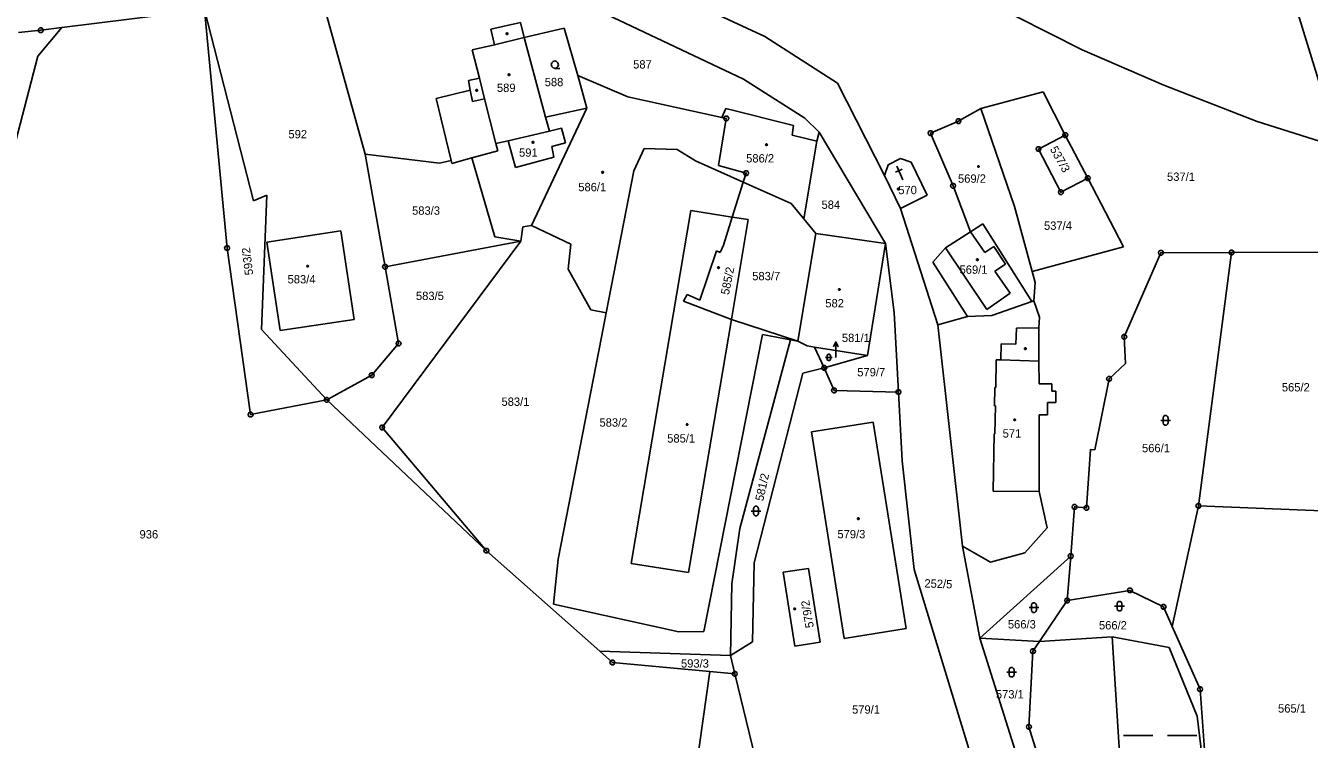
# Model space of a CAD drawing. Extents: x -812394 to -807601, y -1013098 to -1009266.
# Drawn here: x -809265.1 to -809003.5, y -1011807.7 to -1011662.3 of the extents above; entities that cross this region are included whole.
import ezdxf

# ---------------------------------------------------------------- set-up
doc = ezdxf.new("R2010")
doc.units = 0
for name, color, linetype in [('KN_HRANICE', 7, 'Continuous'), ('KN_KULTURY', 7, 'Continuous'), ('KN_MEZNIKY', 7, 'Continuous'), ('KN_PARCELY', 7, 'Continuous'), ('KN_SLUCKY', 7, 'Continuous')]:
    doc.layers.add(name, color=color, linetype=linetype)

# ---------------------------------------------------------------- blocks, each defined once
blk = doc.blocks.new('304')
blk.add_lwpolyline([(0, 0), (-0.38, 0.1), (-0.65, 0.37), (-0.75, 0.74), (-0.65, 1.11), (-0.38, 1.38), (-0.01, 1.48), (0.36, 1.38), (0.63, 1.11), (0.73, 0.73), (0.63, 0.35), (0.36, 0.08), (-0.02, -0.02), (0.98, -0.02)])
blk = doc.blocks.new('316')
for points in [[(-1, 1), (0.27, 1), (1, 1)], [(-0.5, 1.5), (-0.4, 1.79), (-0.15, 1.97), (0.16, 1.97), (0.41, 1.79), (0.51, 1.5), (0.51, 0.5), (0.41, 0.21), (0.16, 0.03), (-0.15, 0.03), (-0.4, 0.21), (-0.5, 0.5), (-0.5, 1.5)]]:
    blk.add_lwpolyline(points)
blk = doc.blocks.new('NAHRADNI_SYMBOL')
blk.add_lwpolyline([(0.09, 0.15), (0.18, 0), (0.09, -0.15), (-0.09, -0.15), (-0.18, 0), (-0.09, 0.15), (0.09, 0.15)])
blk = doc.blocks.new('803')
for p, q in [((-7.5, 0), (-1.5, 0)), ((1.5, 0), (7.5, 0))]:
    blk.add_line(p, q)
blk = doc.blocks.new('10292')
blk.add_line((0, 3), (0, 0))
blk.add_lwpolyline([(-0.5, 2), (0, 3), (0.5, 2)])
blk = doc.blocks.new('402')
blk.add_lwpolyline([(0.09, 0.15), (0.18, 0), (0.09, -0.15), (-0.09, -0.15), (-0.18, 0), (-0.09, 0.15), (0.09, 0.15)])
blk = doc.blocks.new('4091')
for p, q in [((0, 0), (0, 3)), ((0.75, 2), (-0.75, 2))]:
    blk.add_line(p, q)
blk = doc.blocks.new('105')
blk.add_line((-0.12, 0), (0.12, 0))
blk.add_lwpolyline([(0.15, 0.48), (0.4, 0.3), (0.5, 0.01), (0.4, -0.28), (0.15, -0.46), (-0.16, -0.46), (-0.41, -0.28), (-0.51, 0.01), (-0.41, 0.3), (-0.16, 0.48), (0.15, 0.48)])

msp = doc.modelspace()

# ---------------------------------------------------------------- linework, layer by layer
at = {"layer": 'KN_HRANICE'}
for p, q in [((-809015.5, -1011628.37), (-808997.45, -1011687.11)), ((-809118.81, -1011673.24), (-809167.11, -1011650.32)), ((-809144.03, -1011650.78), (-809114.47, -1011664.51)), ((-809204.84, -1011656.21), (-809195.9, -1011688.5)), ((-809257.74, -1011662.73), (-809228.66, -1011659.08)), ((-809218.66, -1011698.01), (-809228.66, -1011659.08)), ((-809228.66, -1011659.08), (-809224.05, -1011707.64)), ((-809164.26, -1011661.71), (-809170.27, -1011663.04)), ((-809164.26, -1011661.71), (-809163.49, -1011664.76)), ((-809063.24, -1011660.46), (-809049.78, -1011667.23)), ((-809266.53, -1011663.7), (-809262.03, -1011663.27)), ((-809262.63, -1011668.57), (-809257.74, -1011662.73)), ((-809262.03, -1011663.27), (-809257.74, -1011662.73)), ((-809170.27, -1011663.04), (-809169.57, -1011666.21)), ((-809163.49, -1011664.76), (-809155.36, -1011662.84)), ((-809163.49, -1011664.76), (-809159.14, -1011680.97)), ((-809155.36, -1011662.84), (-809152.6, -1011672.5)), ((-809114.47, -1011664.51), (-809099.63, -1011674.03)), ((-809174.08, -1011667.28), (-809169.57, -1011666.21)), ((-809174.08, -1011667.28), (-809172.62, -1011673.04)), ((-809049.78, -1011667.23), (-809033.12, -1011674.42)), ((-809269.33, -1011694.44), (-809262.63, -1011668.57)), ((-809174.88, -1011673.53), (-809172.62, -1011673.04)), ((-809142.39, -1011676.83), (-809152.6, -1011672.5)), ((-809152.6, -1011672.5), (-809150.71, -1011679.14)), ((-809181.41, -1011677.14), (-809174.49, -1011675.49)), ((-809174.49, -1011675.49), (-809174.88, -1011673.53)), ((-809106.3, -1011681.14), (-809118.81, -1011673.24)), ((-809090.09, -1011692.88), (-809099.63, -1011674.03)), ((-809033.12, -1011674.42), (-809014.11, -1011681.87)), ((-809178.41, -1011689.79), (-809181.41, -1011677.14)), ((-809123.26, -1011681.02), (-809142.39, -1011676.83)), ((-809070.44, -1011679.2), (-809057.74, -1011675.8)), ((-809057.74, -1011675.8), (-809053.23, -1011684.62)), ((-809162.04, -1011703.02), (-809150.71, -1011679.14)), ((-809150.71, -1011679.14), (-809159.14, -1011680.97)), ((-809123.26, -1011681.02), (-809122.44, -1011679.19)), ((-809122.44, -1011679.19), (-809108.6, -1011682.65)), ((-809074.31, -1011681.39), (-809070.44, -1011679.2)), ((-809063.59, -1011699.18), (-809070.44, -1011679.2)), ((-809159.14, -1011680.97), (-809158.38, -1011683.82)), ((-809123.9, -1011690.84), (-809122.31, -1011681.23)), ((-809122.31, -1011681.23), (-809123.26, -1011681.02)), ((-809108.6, -1011682.65), (-809108.92, -1011684.62)), ((-809103.4, -1011684.01), (-809106.3, -1011681.14)), ((-809080.69, -1011684.21), (-809074.99, -1011681.77)), ((-809074.99, -1011681.77), (-809074.31, -1011681.39)), ((-809014.11, -1011681.87), (-808997.45, -1011687.11)), ((-809169.26, -1011686.36), (-809166.74, -1011685.77)), ((-809166.74, -1011685.77), (-809158.38, -1011683.82)), ((-809108.92, -1011684.62), (-809103.84, -1011685.87)), ((-809103.84, -1011685.87), (-809106.54, -1011701.66)), ((-809103.4, -1011684.01), (-809103.84, -1011685.87)), ((-809103.4, -1011684.01), (-809089.88, -1011706.73)), ((-809076.1, -1011694.95), (-809080.69, -1011684.21)), ((-809053.23, -1011684.62), (-809058.69, -1011687.46)), ((-809048.65, -1011693.42), (-809053.23, -1011684.62)), ((-809195.9, -1011688.5), (-809180.76, -1011690.33)), ((-809195.9, -1011688.5), (-809191.85, -1011711.45)), ((-809174.17, -1011689.22), (-809168.89, -1011687.82)), ((-809169.26, -1011686.36), (-809168.89, -1011687.82)), ((-809139.05, -1011687.35), (-809141.13, -1011691.93)), ((-809132.32, -1011687.55), (-809139.05, -1011687.35)), ((-809128.57, -1011689.88), (-809132.32, -1011687.55)), ((-809058.69, -1011687.46), (-809054.11, -1011696.26)), ((-809180.76, -1011690.33), (-809178.41, -1011689.79)), ((-809178.41, -1011689.79), (-809178.26, -1011690.42)), ((-809178.26, -1011690.42), (-809174.17, -1011689.22)), ((-809174.17, -1011689.22), (-809169.49, -1011705.38)), ((-809118.86, -1011694.22), (-809128.57, -1011689.88)), ((-809118.27, -1011692.36), (-809123.9, -1011690.84)), ((-809090.09, -1011692.88), (-809089.34, -1011690.67)), ((-809089.34, -1011690.67), (-809086.85, -1011689.4)), ((-809086.85, -1011689.4), (-809084.66, -1011690.15)), ((-809084.66, -1011690.15), (-809081.39, -1011696.85)), ((-809141.13, -1011691.93), (-809146.78, -1011720.87)), ((-809118.86, -1011694.22), (-809118.27, -1011692.36)), ((-809086.82, -1011699.58), (-809090.09, -1011692.88)), ((-809054.11, -1011696.26), (-809048.65, -1011693.42)), ((-809048.65, -1011693.42), (-809041.37, -1011707.4)), ((-809121.11, -1011701.32), (-809118.86, -1011694.22)), ((-809109.13, -1011698.56), (-809118.86, -1011694.22)), ((-809072.55, -1011704.3), (-809076.1, -1011694.95)), ((-809215.97, -1011696.83), (-809218.66, -1011698.01)), ((-809217.07, -1011724.24), (-809215.97, -1011696.83)), ((-809106.54, -1011701.66), (-809109.13, -1011698.56)), ((-809081.39, -1011696.85), (-809086.82, -1011699.58)), ((-809059.99, -1011712.39), (-809063.59, -1011699.18)), ((-809129.54, -1011699.97), (-809133.14, -1011721.27)), ((-809121.11, -1011701.32), (-809129.54, -1011699.97)), ((-809121.11, -1011701.32), (-809122.92, -1011707.03)), ((-809121.28, -1011722.18), (-809117.84, -1011701.84)), ((-809117.84, -1011701.84), (-809121.11, -1011701.32)), ((-809104.04, -1011704.66), (-809106.54, -1011701.66)), ((-809079.24, -1011723.27), (-809086.82, -1011699.58)), ((-809215.97, -1011706.41), (-809200.9, -1011704.12)), ((-809200.9, -1011704.12), (-809198.16, -1011722.17)), ((-809163.75, -1011703.34), (-809164.16, -1011706.25)), ((-809162.04, -1011703.02), (-809163.75, -1011703.34)), ((-809162.04, -1011703.02), (-809154.01, -1011706.83)), ((-809077.65, -1011707.56), (-809072.55, -1011704.3)), ((-809072.55, -1011704.3), (-809070.01, -1011702.67)), ((-809070.01, -1011702.67), (-809060.03, -1011718.52)), ((-809213.22, -1011724.44), (-809215.97, -1011706.41)), ((-809164.16, -1011706.25), (-809192.44, -1011744.19)), ((-809191.85, -1011711.45), (-809164.16, -1011706.25)), ((-809164.16, -1011706.25), (-809169.49, -1011705.38)), ((-809154.01, -1011706.83), (-809154.57, -1011711.95)), ((-809122.92, -1011707.03), (-809123.54, -1011708.51)), ((-809104.04, -1011704.66), (-809107.75, -1011726.64)), ((-809089.88, -1011706.73), (-809104.04, -1011704.66)), ((-809093.54, -1011729.56), (-809089.88, -1011706.73)), ((-809088.11, -1011720.75), (-809089.88, -1011706.73)), ((-809224.05, -1011707.64), (-809219.25, -1011741.58)), ((-809124.3, -1011708.21), (-809127.72, -1011718.26)), ((-809123.54, -1011708.51), (-809124.3, -1011708.21)), ((-809080.26, -1011710.48), (-809077.65, -1011707.56)), ((-809041.37, -1011707.4), (-809059.99, -1011712.39)), ((-809041.21, -1011725.74), (-809033.74, -1011708.6)), ((-809033.74, -1011708.6), (-809019.35, -1011708.55)), ((-809019.35, -1011708.55), (-809026.09, -1011760.16)), ((-809019.35, -1011708.55), (-808992.34, -1011708.44)), ((-809191.85, -1011711.45), (-809189.09, -1011727.11)), ((-809154.57, -1011711.95), (-809149.9, -1011720.22)), ((-809080.26, -1011710.48), (-809073.13, -1011721.6)), ((-809059.99, -1011712.39), (-809059.38, -1011714.65)), ((-809059.38, -1011714.65), (-809059.65, -1011718.39)), ((-809130.26, -1011717.12), (-809131.05, -1011718.48)), ((-809127.72, -1011718.26), (-809130.26, -1011717.12)), ((-809131.05, -1011718.48), (-809121.28, -1011722.18)), ((-809060.03, -1011718.52), (-809068.19, -1011721.35)), ((-809059.65, -1011718.39), (-809060.03, -1011718.52)), ((-809059.65, -1011718.39), (-809058.51, -1011721.71)), ((-809198.16, -1011722.17), (-809213.22, -1011724.44)), ((-809149.9, -1011720.22), (-809146.78, -1011720.87)), ((-809146.78, -1011720.87), (-809147.74, -1011725.8)), ((-809133.14, -1011721.27), (-809141.69, -1011771.9)), ((-809130.02, -1011773.75), (-809121.28, -1011722.18)), ((-809121.28, -1011722.18), (-809107.75, -1011726.64)), ((-809087.23, -1011736.98), (-809088.11, -1011720.75)), ((-809079.24, -1011723.27), (-809073.13, -1011721.6)), ((-809068.19, -1011721.35), (-809073.13, -1011721.6)), ((-809058.51, -1011721.71), (-809058.62, -1011723.92)), ((-809217.07, -1011724.24), (-809203.75, -1011738.59)), ((-809126.88, -1011785.75), (-809114.95, -1011725.23)), ((-809114.95, -1011725.23), (-809109.23, -1011726.35)), ((-809074.17, -1011768.37), (-809079.24, -1011723.27)), ((-809058.62, -1011723.92), (-809058.6, -1011730.69)), ((-809189.09, -1011727.11), (-809194.56, -1011733.56)), ((-809147.74, -1011725.8), (-809156.57, -1011771.05)), ((-809119.53, -1011764.8), (-809109.23, -1011726.35)), ((-809109.23, -1011726.35), (-809107.75, -1011726.64)), ((-809107.75, -1011726.64), (-809105.87, -1011727.54)), ((-809105.87, -1011727.54), (-809104.33, -1011727.8)), ((-809104.33, -1011727.8), (-809093.54, -1011729.56)), ((-809102.34, -1011732.05), (-809104.33, -1011727.8)), ((-809040.99, -1011731.14), (-809041.21, -1011725.74)), ((-809102.34, -1011732.05), (-809093.54, -1011729.56)), ((-809106.72, -1011733.12), (-809116.67, -1011771.8)), ((-809102.34, -1011732.05), (-809106.72, -1011733.12)), ((-809100.36, -1011736.65), (-809102.34, -1011732.05)), ((-809058.6, -1011730.69), (-809058.59, -1011735.29)), ((-809044.31, -1011734.3), (-809040.99, -1011731.14)), ((-809194.56, -1011733.56), (-809203.75, -1011738.59)), ((-809058.59, -1011735.29), (-809055.99, -1011735.28)), ((-809055.99, -1011735.28), (-809055.99, -1011736.83)), ((-809047.24, -1011748.72), (-809044.31, -1011734.3)), ((-809087.23, -1011736.98), (-809100.36, -1011736.65)), ((-809087.23, -1011736.98), (-809086.47, -1011750.97)), ((-809055.99, -1011736.83), (-809055.19, -1011736.83)), ((-809055.19, -1011736.83), (-809055.18, -1011739.08)), ((-809219.25, -1011741.58), (-809203.75, -1011738.59)), ((-809203.75, -1011738.59), (-809171.21, -1011769.31)), ((-809055.18, -1011739.08), (-809056.83, -1011739.09)), ((-809056.83, -1011739.09), (-809056.83, -1011741.64)), ((-809104.96, -1011745.11), (-809092.42, -1011743.1)), ((-809092.42, -1011743.1), (-809085.69, -1011785.15)), ((-809056.83, -1011741.64), (-809058.58, -1011741.64)), ((-809058.55, -1011757.24), (-809058.58, -1011741.64)), ((-809171.21, -1011769.31), (-809192.44, -1011744.19)), ((-809098.28, -1011787.19), (-809104.96, -1011745.11)), ((-809048.93, -1011760.57), (-809048.08, -1011748.66)), ((-809048.08, -1011748.66), (-809047.24, -1011748.72)), ((-809084.06, -1011773.13), (-809086.47, -1011750.97)), ((-809058.55, -1011757.24), (-809056.9, -1011764.63)), ((-809052.13, -1011770.41), (-809051.33, -1011760.4)), ((-809051.33, -1011760.4), (-809048.93, -1011760.57)), ((-809026.09, -1011760.16), (-809031.43, -1011784.75)), ((-809026.09, -1011760.16), (-808975.59, -1011762.27)), ((-809056.9, -1011764.63), (-809061.5, -1011769.71)), ((-809121.22, -1011776.06), (-809119.53, -1011764.8)), ((-809148.1, -1011789.81), (-809171.21, -1011769.31)), ((-809070.64, -1011787.15), (-809074.17, -1011768.37)), ((-809068.47, -1011771.64), (-809074.17, -1011768.37)), ((-809061.5, -1011769.71), (-809068.47, -1011771.64)), ((-809156.57, -1011771.05), (-809157.53, -1011780.19)), ((-809141.69, -1011771.9), (-809130.02, -1011773.75)), ((-809116.67, -1011771.8), (-809116.97, -1011787.86)), ((-809070.64, -1011787.15), (-809052.13, -1011770.41)), ((-809052.13, -1011770.41), (-809052.85, -1011779.47)), ((-809110.7, -1011773.71), (-809105.55, -1011772.9)), ((-809108.37, -1011788.76), (-809110.7, -1011773.71)), ((-809105.55, -1011772.9), (-809103.18, -1011787.93)), ((-809068.2, -1011824.99), (-809084.06, -1011773.13)), ((-809121.45, -1011790.63), (-809121.22, -1011776.06)), ((-809052.85, -1011779.47), (-809040.06, -1011777.39)), ((-809040.06, -1011777.39), (-809033.21, -1011780.74)), ((-809157.53, -1011780.19), (-809131.97, -1011785.87)), ((-809058.49, -1011787.83), (-809052.85, -1011779.47)), ((-809033.21, -1011780.74), (-809031.43, -1011784.75)), ((-809085.69, -1011785.15), (-809098.28, -1011787.19)), ((-809031.43, -1011784.75), (-809025.76, -1011797.55)), ((-809131.97, -1011785.87), (-809126.88, -1011785.75)), ((-809116.97, -1011787.86), (-809121.45, -1011790.63)), ((-809103.18, -1011787.93), (-809108.37, -1011788.76)), ((-809070.64, -1011787.15), (-809058.49, -1011787.83)), ((-809059.59, -1011822.15), (-809070.64, -1011787.15)), ((-809059.83, -1011789.81), (-809058.49, -1011787.83)), ((-809058.49, -1011787.83), (-809043.65, -1011786.86)), ((-809043.65, -1011786.86), (-809032.04, -1011789.04)), ((-809039.91, -1011846.09), (-809043.65, -1011786.86)), ((-809121.45, -1011790.63), (-809148.1, -1011789.81)), ((-809145.51, -1011792.11), (-809148.1, -1011789.81)), ((-809120.59, -1011794.42), (-809121.45, -1011790.63)), ((-809059.83, -1011789.81), (-809060.63, -1011805.19)), ((-809032.04, -1011789.04), (-809026.36, -1011802.99)), ((-809145.51, -1011792.11), (-809125.69, -1011793.95)), ((-809125.69, -1011793.95), (-809130.74, -1011830.07)), ((-809125.69, -1011793.95), (-809120.59, -1011794.42)), ((-809120.59, -1011794.42), (-809112.8, -1011826.22)), ((-809025.76, -1011797.55), (-809023.89, -1011823.5)), ((-809026.36, -1011802.99), (-809023.89, -1011823.5)), ((-809060.63, -1011805.19), (-809052.86, -1011830.28))]:
    msp.add_line(p, q, dxfattribs=at)
at = {"layer": 'KN_PARCELY'}
msp.add_line((-809100, -1011729.97), (-809100, -1011729.78), dxfattribs=at)
at = {"layer": 'KN_SLUCKY'}
for p, q in [((-809169.57, -1011666.21), (-809163.49, -1011664.76)), ((-809172.62, -1011673.04), (-809171.56, -1011677.23)), ((-809174.49, -1011675.49), (-809174.02, -1011677.78)), ((-809174.02, -1011677.78), (-809171.56, -1011677.23)), ((-809171.56, -1011677.23), (-809169.26, -1011686.36)), ((-809158.38, -1011683.82), (-809155.87, -1011683.24)), ((-809155.87, -1011683.24), (-809155.08, -1011686.23)), ((-809165.28, -1011691.23), (-809166.74, -1011685.77)), ((-809155.08, -1011686.23), (-809157.86, -1011686.96)), ((-809157.86, -1011686.96), (-809157.43, -1011689.13)), ((-809157.43, -1011689.13), (-809165.28, -1011691.23)), ((-809072.55, -1011704.3), (-809069.64, -1011708.56)), ((-809077.65, -1011707.56), (-809069.21, -1011720.16)), ((-809067.82, -1011707.33), (-809069.64, -1011708.56)), ((-809065.41, -1011710.9), (-809067.82, -1011707.33)), ((-809067.6, -1011712.38), (-809065.41, -1011710.9)), ((-809064.48, -1011716.84), (-809067.6, -1011712.38)), ((-809069.21, -1011720.16), (-809064.48, -1011716.84)), ((-809063.19, -1011723.98), (-809063.29, -1011727.23)), ((-809058.62, -1011723.92), (-809063.19, -1011723.98)), ((-809066.29, -1011727.14), (-809066.39, -1011730.44)), ((-809063.29, -1011727.23), (-809066.29, -1011727.14)), ((-809067.33, -1011730.41), (-809067.42, -1011736.07)), ((-809066.39, -1011730.44), (-809067.33, -1011730.41)), ((-809058.6, -1011730.69), (-809066.39, -1011730.44)), ((-809067.62, -1011736.07), (-809067.67, -1011739.78)), ((-809067.42, -1011736.07), (-809067.62, -1011736.07)), ((-809067.67, -1011739.78), (-809067.47, -1011739.78)), ((-809067.47, -1011739.78), (-809067.56, -1011745.49)), ((-809067.76, -1011745.49), (-809067.94, -1011757.16)), ((-809067.56, -1011745.49), (-809067.76, -1011745.49)), ((-809058.55, -1011757.24), (-809067.94, -1011757.16))]:
    msp.add_line(p, q, dxfattribs=at)

# ---------------------------------------------------------------- block references
at = {"layer": 'KN_KULTURY'}
for name, p in [('402', (-809166.99, -1011663.96)), ('304', (-809157.25, -1011671)), ('402', (-809166.59, -1011672.32)), ('402', (-809173.19, -1011675.51)), ('402', (-809161.73, -1011686.1)), ('NAHRADNI_SYMBOL', (-809114.12, -1011686.56)), ('NAHRADNI_SYMBOL', (-809070.92, -1011691.03)), ('NAHRADNI_SYMBOL', (-809147.53, -1011692.2)), ('402', (-809087.25, -1011695.61)), ('402', (-809207.64, -1011711.32)), ('402', (-809123.9, -1011711.64)), ('402', (-809071.16, -1011710)), ('402', (-809099.29, -1011716.08)), ('402', (-809061.37, -1011728.13)), ('402', (-809130.29, -1011743.58)), ('402', (-809063.54, -1011742.62)), ('316', (-809032.79, -1011743.75)), ('316', (-809116.27, -1011762.23)), ('402', (-809095.4, -1011762.79)), ('316', (-809059.62, -1011781.9)), ('316', (-809042.19, -1011781.6)), ('402', (-809108.37, -1011781.14)), ('316', (-809064.17, -1011795.07)), ('803', (-809033.9, -1011806.98))]:
    msp.add_blockref(name, p, dxfattribs=at)
at = {"layer": 'KN_KULTURY', "rotation": 24.178819}
msp.add_blockref('4091', (-809086.34, -1011693.71), dxfattribs=at)
at = {"layer": 'KN_KULTURY', "xscale": 0.67, "yscale": 0.67}
msp.add_blockref('316', (-809101.4, -1011730.59), dxfattribs=at)
at = {"layer": 'KN_MEZNIKY'}
for p in [(-809262.03, -1011663.27), (-809122.31, -1011681.23), (-809074.99, -1011681.77), (-809080.69, -1011684.21), (-809053.23, -1011684.62), (-809058.69, -1011687.46), (-809118.27, -1011692.36), (-809048.65, -1011693.42), (-809076.1, -1011694.95), (-809054.11, -1011696.26), (-809224.05, -1011707.64), (-809033.74, -1011708.6), (-809019.35, -1011708.55), (-809191.85, -1011711.45), (-809041.21, -1011725.74), (-809189.09, -1011727.11), (-809194.56, -1011733.56), (-809102.34, -1011732.05), (-809044.31, -1011734.3), (-809203.75, -1011738.59), (-809100.36, -1011736.65), (-809087.23, -1011736.98), (-809219.25, -1011741.58), (-809192.44, -1011744.19), (-809051.33, -1011760.4), (-809048.93, -1011760.57), (-809026.09, -1011760.16), (-809171.21, -1011769.31), (-809052.13, -1011770.41), (-809040.06, -1011777.39), (-809052.85, -1011779.47), (-809033.21, -1011780.74), (-809059.83, -1011789.81), (-809145.51, -1011792.11), (-809120.59, -1011794.42), (-809025.76, -1011797.55), (-809060.63, -1011805.19)]:
    msp.add_blockref('105', p, dxfattribs=at)
at = {"layer": 'KN_PARCELY'}
msp.add_blockref('10292', (-809100, -1011729.78), dxfattribs=at)

# ---------------------------------------------------------------- texts
for s, p in [('587', (-809141.3, -1011671.06)), ('588', (-809159.32, -1011674.66)), ('589', (-809169.06, -1011675.83)), ('592', (-809211.55, -1011685.28)), ('591', (-809164.55, -1011689.03)), ('586/2', (-809118.27, -1011690.2)), ('569/2', (-809075.1, -1011694.33)), ('537/1', (-809032.5, -1011693.95)), ('586/1', (-809152.48, -1011696.06)), ('570', (-809087.27, -1011696.66)), ('583/3', (-809186.35, -1011700.85)), ('584', (-809102.91, -1011699.65)), ('537/4', (-809057.57, -1011703.92)), ('569/1', (-809074.78, -1011712.88)), ('583/4', (-809211.72, -1011714.84)), ('583/7', (-809117.03, -1011714.2)), ('583/5', (-809185.56, -1011718.23)), ('582', (-809102.14, -1011719.73)), ('581/1', (-809098.76, -1011726.78)), ('579/7', (-809095.63, -1011733.78)), ('565/2', (-809009.1, -1011736.85)), ('583/1', (-809168.13, -1011739.79)), ('583/2', (-809148.16, -1011744.03)), ('585/1', (-809134.36, -1011747.27)), ('571', (-809066, -1011746.26)), ('566/1', (-809037.6, -1011749.24)), ('936', (-809241.89, -1011766.81)), ('579/3', (-809099.67, -1011766.78)), ('566/3', (-809064.93, -1011785.15)), ('566/2', (-809046.37, -1011785.35)), ('593/3', (-809131.55, -1011793.13)), ('573/1', (-809067.38, -1011799.41)), ('579/1', (-809096.69, -1011802.51)), ('565/1', (-809009.88, -1011802.29))]:
    msp.add_text(s, height=1.7, dxfattribs=at).set_placement(p)
for s, height, rotation, p in [('537/3', 1.7, 299.256, (-809056.43, -1011687.47)), ('593/2', 1.7, 97.059, (-809218.7, -1011713.07)), ('585/2', 1.7, 78.495, (-809121.8, -1011717.27)), ('581/1', 0.1, 351.223, (-809100.23, -1011729.94)), ('581/2', 1.7, 77.521, (-809114.8, -1011759.31)), ('252/5', 1.7, 357.927, (-809081.97, -1011776.79)), ('579/2', 1.7, 99.924, (-809104.46, -1011784.89))]:
    msp.add_text(s, height=height, rotation=rotation, dxfattribs=at).set_placement(p)

doc.saveas('drawing.dxf')
